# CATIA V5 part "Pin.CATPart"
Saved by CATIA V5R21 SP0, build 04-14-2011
Part number: Pin
Bounding box of the stored display mesh (mm): x -10.997 to 10.997, y 0 to 38, z -10.885 to 10.885
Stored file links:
  D:\CATIA V5R21 E-RESOURCES\CATIA-V5R21\catia-v5r21-Prts\c12_catia_v5r21_prt\c12_catia_v5r21figr_12-49\Pin.CATPart
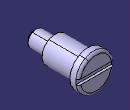
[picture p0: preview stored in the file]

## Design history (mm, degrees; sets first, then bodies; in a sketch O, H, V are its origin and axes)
Body1 (main body)
  Sketch1 on yz-plane, origin (0, 0, 0), H (0, 1, 0), V (0, 0, 1)
    line L1 (0, 0) -> (0, 5)
    line L2 (0, 5) -> (13, 5)
    line L3 (13, 5) -> (13, 8)
    line L4 (13, 8) -> (33, 8)
    line L5 (33, 8) -> (33, 11)
    line L6 (33, 11) -> (38, 11)
    line L7 (38, 11) -> (38, 0)
    point P7 (38, 0)
    line L8 (38, 0) -> (0, 0)
    distance L8 L6 = 11
    distance L4 L8 = 8
    length L8 = 38
    distance L2 L8 = 5
    length L6 = 5
    length L4 = 20
    vertical: L1 V, L3 V, L5 V, L7 V
    horizontal: L2 H, L4 H, L8 H, L6 H
    coincidence: P7 H
  Shaft1: profile Sketch1, axis edge of Sketch1, angle 360
  Chamfer1: length 1.5, angle 45, on 1 edge
  Fillet1: radius 1.5, on 1 edge
  Sketch2 on face of Shaft1, origin (0, 38, 0), H (-1, 0, 0), V (0, 0, 1)
    line L1 (-15.6575, 1.5) -> (20.3727, 1.5)
    line L2 (20.3727, 1.5) -> (20.3727, -1.5)
    line L3 (20.3727, -1.5) -> (-15.6575, -1.5)
    line L4 (-15.6575, -1.5) -> (-15.6575, 1.5)
    distance H L3 = 1.5
    length L4 = 3
    horizontal: L1 H, L3 H
    vertical: L2 V, L4 V
  Pocket1: profile Sketch2, direction (0, -1, 0), length 1.5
